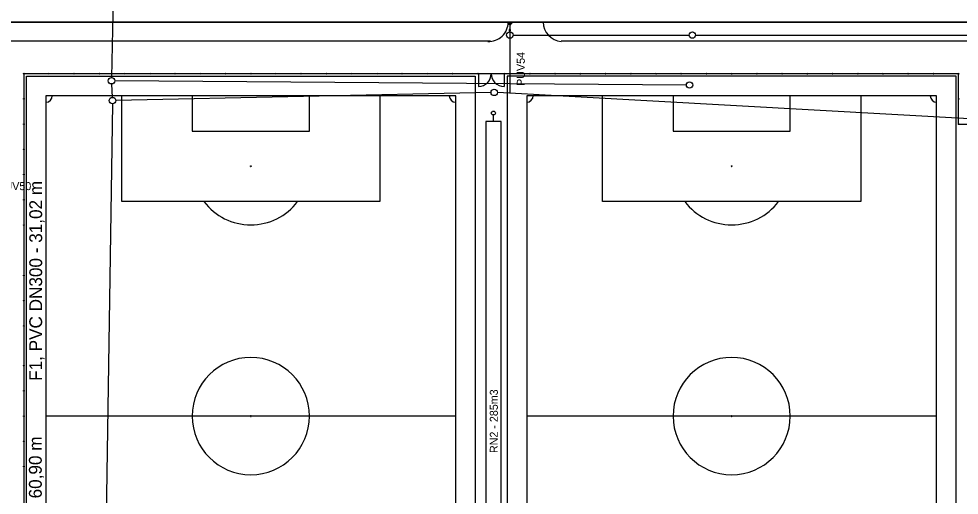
# Model space of a CAD drawing. Extents: x -264234 to -263604, y -1242346 to -1242049.
# Drawn here: x -264118.9 to -263972, y -1242253.3 to -1242179 of the extents above; entities that cross this region are included whole.
import ezdxf

# ---------------------------------------------------------------- set-up
doc = ezdxf.new("R2010")
doc.units = 0
for name, color, linetype in [('KFA_DAZDOVA_KANALIZACIA_vetva_F_popis', 7, 'Continuous'), ('KFA_JESTV_IS_DSP_-_KANAL_DAZD', 7, 'Continuous'), ('KFA_SITUACIA_DSP', 7, 'Continuous'), ('KFA_SO_40-2-II_DK_PRIPOJKY_UV_PROJEKT', 7, 'Continuous'), ('KFA_SO_40-2-II_DK_PRIPOJKY_UV_PROJEKT_popis', 7, 'Continuous')]:
    doc.layers.add(name, color=color, linetype=linetype)

msp = doc.modelspace()

# ---------------------------------------------------------------- linework, layer by layer
at = {"layer": 'KFA_JESTV_IS_DSP_-_KANAL_DAZD'}
for p, q in [((-264103.36, -1242140.62), (-264104.36, -1242188.14)), ((-264014.6, -1242189.3), (-264103.87, -1242188.64)), ((-264104.37, -1242189.14), (-264104.25, -1242191.23)), ((-264045.1, -1242190.47), (-264103.72, -1242191.72)), ((-263970.37, -1242194.6), (-264044.1, -1242190.48)), ((-264104.23, -1242192.23), (-264105.48, -1242275.06))]:
    msp.add_line(p, q, dxfattribs=at)
for centre in [(-264104.37, -1242188.64), (-264014.1, -1242189.3), (-264044.6, -1242190.46), (-264104.22, -1242191.73)]:
    msp.add_circle(centre, 0.5, dxfattribs=at)
at = {"layer": 'KFA_SITUACIA_DSP'}
for p, q in [((-264077.23, -1242179.48), (-264131.57, -1242179.48)), ((-264131.57, -1242179.48), (-263959.47, -1242179.48)), ((-263959.47, -1242179.48), (-264131.57, -1242179.48)), ((-263959.47, -1242179.48), (-264077.23, -1242179.48)), ((-264042.42, -1242179.48), (-264041.92, -1242179.48)), ((-264042.42, -1242179.77), (-264042.42, -1242179.48)), ((-264042.42, -1242179.48), (-264041.92, -1242179.77)), ((-264042.42, -1242179.48), (-264041.92, -1242179.77)), ((-264041.92, -1242179.48), (-264042.42, -1242179.48)), ((-264041.92, -1242179.77), (-264042.42, -1242179.77)), ((-264042.17, -1242179.97), (-264042.17, -1242181)), ((-264041.92, -1242179.48), (-264041.92, -1242179.77)), ((-264041.92, -1242179.77), (-264041.92, -1242179.48)), ((-264041.67, -1242181.5), (-264014.16, -1242181.5)), ((-264013.16, -1242181.5), (-263964.16, -1242181.5)), ((-264045.2, -1242182.48), (-264131.57, -1242182.48)), ((-263960.12, -1242182.48), (-264034.16, -1242182.48)), ((-264118.01, -1242187.53), (-264118.13, -1242187.53)), ((-264118.07, -1242187.59), (-264118.07, -1242187.47)), ((-263972.07, -1242187.53), (-264118.07, -1242187.53)), ((-264118.07, -1242187.53), (-264118.07, -1242294.43)), ((-264114.07, -1242187.53), (-264114.19, -1242187.53)), ((-264114.13, -1242187.59), (-264114.13, -1242187.47)), ((-264110.13, -1242187.53), (-264110.25, -1242187.53)), ((-264110.19, -1242187.59), (-264110.19, -1242187.47)), ((-264106.19, -1242187.53), (-264106.31, -1242187.53)), ((-264106.25, -1242187.59), (-264106.25, -1242187.47)), ((-264102.25, -1242187.53), (-264102.37, -1242187.53)), ((-264102.31, -1242187.59), (-264102.31, -1242187.47)), ((-264098.31, -1242187.53), (-264098.43, -1242187.53)), ((-264098.37, -1242187.59), (-264098.37, -1242187.47)), ((-264094.37, -1242187.53), (-264094.49, -1242187.53)), ((-264094.43, -1242187.59), (-264094.43, -1242187.47)), ((-264090.44, -1242187.53), (-264090.56, -1242187.53)), ((-264090.5, -1242187.59), (-264090.5, -1242187.47)), ((-264086.5, -1242187.53), (-264086.62, -1242187.53)), ((-264086.56, -1242187.59), (-264086.56, -1242187.47)), ((-264082.56, -1242187.53), (-264082.68, -1242187.53)), ((-264082.62, -1242187.59), (-264082.62, -1242187.47)), ((-264078.62, -1242187.53), (-264078.74, -1242187.53)), ((-264078.68, -1242187.59), (-264078.68, -1242187.47)), ((-264074.68, -1242187.53), (-264074.8, -1242187.53)), ((-264074.74, -1242187.59), (-264074.74, -1242187.47)), ((-264070.74, -1242187.53), (-264070.86, -1242187.53)), ((-264070.8, -1242187.59), (-264070.8, -1242187.47)), ((-264066.8, -1242187.53), (-264066.92, -1242187.53)), ((-264066.86, -1242187.59), (-264066.86, -1242187.47)), ((-264062.86, -1242187.53), (-264062.98, -1242187.53)), ((-264062.92, -1242187.59), (-264062.92, -1242187.47)), ((-264058.92, -1242187.53), (-264059.04, -1242187.53)), ((-264058.98, -1242187.59), (-264058.98, -1242187.47)), ((-264054.99, -1242187.53), (-264055.11, -1242187.53)), ((-264055.05, -1242187.59), (-264055.05, -1242187.47)), ((-264051.05, -1242187.53), (-264051.17, -1242187.53)), ((-264051.11, -1242187.59), (-264051.11, -1242187.47)), ((-264047.11, -1242187.53), (-264047.23, -1242187.53)), ((-264047.17, -1242187.59), (-264047.17, -1242187.47)), ((-264047.07, -1242187.53), (-264047.07, -1242189.53)), ((-264044.57, -1242187.53), (-264045.57, -1242187.53)), ((-264043.07, -1242187.53), (-264043.07, -1242189.53)), ((-264042.91, -1242187.53), (-264043.03, -1242187.53)), ((-264042.97, -1242187.59), (-264042.97, -1242187.47)), ((-264039.09, -1242187.53), (-264038.97, -1242187.53)), ((-264039.03, -1242187.59), (-264039.03, -1242187.47)), ((-264035.15, -1242187.53), (-264035.03, -1242187.53)), ((-264035.09, -1242187.59), (-264035.09, -1242187.47)), ((-264031.21, -1242187.53), (-264031.09, -1242187.53)), ((-264031.15, -1242187.59), (-264031.15, -1242187.47)), ((-264027.27, -1242187.53), (-264027.15, -1242187.53)), ((-264027.21, -1242187.59), (-264027.21, -1242187.47)), ((-264023.33, -1242187.53), (-264023.21, -1242187.53)), ((-264023.27, -1242187.59), (-264023.27, -1242187.47)), ((-264019.39, -1242187.53), (-264019.27, -1242187.53)), ((-264019.33, -1242187.59), (-264019.33, -1242187.47)), ((-264015.46, -1242187.53), (-264015.34, -1242187.53)), ((-264015.4, -1242187.59), (-264015.4, -1242187.47)), ((-264011.52, -1242187.53), (-264011.4, -1242187.53)), ((-264011.46, -1242187.59), (-264011.46, -1242187.47)), ((-264007.58, -1242187.53), (-264007.46, -1242187.53)), ((-264007.52, -1242187.59), (-264007.52, -1242187.47)), ((-264003.64, -1242187.53), (-264003.52, -1242187.53)), ((-264003.58, -1242187.59), (-264003.58, -1242187.47)), ((-263999.7, -1242187.53), (-263999.58, -1242187.53)), ((-263999.64, -1242187.59), (-263999.64, -1242187.47)), ((-263995.76, -1242187.53), (-263995.64, -1242187.53)), ((-263995.7, -1242187.59), (-263995.7, -1242187.47)), ((-263991.82, -1242187.53), (-263991.7, -1242187.53)), ((-263991.76, -1242187.59), (-263991.76, -1242187.47)), ((-263987.88, -1242187.53), (-263987.76, -1242187.53)), ((-263987.82, -1242187.59), (-263987.82, -1242187.47)), ((-263983.94, -1242187.53), (-263983.82, -1242187.53)), ((-263983.88, -1242187.59), (-263983.88, -1242187.47)), ((-263980.01, -1242187.53), (-263979.89, -1242187.53)), ((-263979.95, -1242187.59), (-263979.95, -1242187.47)), ((-263976.07, -1242187.53), (-263975.95, -1242187.53)), ((-263976.01, -1242187.59), (-263976.01, -1242187.47)), ((-263972.13, -1242187.53), (-263972.01, -1242187.53)), ((-263972.07, -1242187.59), (-263972.07, -1242187.47)), ((-263972.07, -1242195.41), (-263972.07, -1242187.53)), ((-264118.01, -1242191.47), (-264118.13, -1242191.47)), ((-264118.07, -1242191.41), (-264118.07, -1242191.53)), ((-264050.62, -1242190.98), (-264114.62, -1242190.98)), ((-264114.62, -1242190.98), (-264114.62, -1242290.98)), ((-264102.78, -1242207.48), (-264102.78, -1242190.98)), ((-264091.78, -1242190.98), (-264091.78, -1242196.48)), ((-264073.46, -1242196.48), (-264073.46, -1242190.98)), ((-264062.46, -1242190.98), (-264062.46, -1242207.48)), ((-264050.62, -1242290.98), (-264050.62, -1242190.98)), ((-263975.52, -1242190.98), (-264039.52, -1242190.98)), ((-264039.52, -1242190.98), (-264039.52, -1242290.98)), ((-264027.68, -1242207.48), (-264027.68, -1242190.98)), ((-264016.68, -1242190.98), (-264016.68, -1242196.48)), ((-263998.36, -1242196.48), (-263998.36, -1242190.98)), ((-263987.36, -1242190.98), (-263987.36, -1242207.48)), ((-263975.52, -1242290.98), (-263975.52, -1242190.98)), ((-263972.13, -1242191.47), (-263972.01, -1242191.47)), ((-263972.07, -1242191.41), (-263972.07, -1242191.53)), ((-264044.73, -1242194.98), (-264044.73, -1242193.98)), ((-264118.01, -1242195.41), (-264118.13, -1242195.41)), ((-264118.07, -1242195.35), (-264118.07, -1242195.47)), ((-264043.53, -1242194.98), (-264045.93, -1242194.98)), ((-264045.93, -1242194.98), (-264045.93, -1242293.98)), ((-264043.53, -1242293.98), (-264043.53, -1242194.98)), ((-263972.07, -1242195.41), (-263967.42, -1242195.41)), ((-264091.78, -1242196.48), (-264073.46, -1242196.48)), ((-264016.68, -1242196.48), (-263998.36, -1242196.48)), ((-264118.01, -1242199.34), (-264118.13, -1242199.34)), ((-264118.07, -1242199.28), (-264118.07, -1242199.4)), ((-264118.01, -1242203.28), (-264118.13, -1242203.28)), ((-264118.07, -1242203.22), (-264118.07, -1242203.34)), ((-264118.01, -1242207.22), (-264118.13, -1242207.22)), ((-264118.07, -1242207.16), (-264118.07, -1242207.28)), ((-264062.46, -1242207.48), (-264102.78, -1242207.48)), ((-263987.36, -1242207.48), (-264027.68, -1242207.48)), ((-264118.01, -1242211.16), (-264118.13, -1242211.16)), ((-264118.07, -1242211.1), (-264118.07, -1242211.22)), ((-264118.01, -1242219.03), (-264118.13, -1242219.03)), ((-264118.07, -1242218.97), (-264118.07, -1242219.09)), ((-264118.01, -1242222.97), (-264118.13, -1242222.97)), ((-264118.07, -1242222.91), (-264118.07, -1242223.03)), ((-264118.01, -1242226.91), (-264118.13, -1242226.91)), ((-264118.07, -1242226.85), (-264118.07, -1242226.97)), ((-264118.01, -1242233.11), (-264118.13, -1242233.11)), ((-264118.07, -1242233.05), (-264118.07, -1242233.17)), ((-264118.01, -1242237.04), (-264118.13, -1242237.04)), ((-264118.07, -1242236.98), (-264118.07, -1242237.1)), ((-264118.01, -1242240.98), (-264118.13, -1242240.98)), ((-264118.07, -1242241.04), (-264118.07, -1242240.92)), ((-264050.62, -1242240.98), (-264114.62, -1242240.98)), ((-263975.52, -1242240.98), (-264039.52, -1242240.98)), ((-264118.01, -1242244.92), (-264118.13, -1242244.92)), ((-264118.07, -1242244.98), (-264118.07, -1242244.86)), ((-264118.01, -1242248.86), (-264118.13, -1242248.86)), ((-264118.07, -1242248.92), (-264118.07, -1242248.8))]:
    msp.add_line(p, q, dxfattribs=at)
for points in [[(-264117.67, -1242187.93), (-264047.57, -1242187.93), (-264047.57, -1242294.03), (-264117.67, -1242294.03)], [(-264042.57, -1242294.03), (-263972.47, -1242294.03), (-263972.47, -1242187.93), (-264042.57, -1242187.93)]]:
    msp.add_lwpolyline(points, close=True, dxfattribs=at)
for centre, radius in [((-264042.17, -1242179.87), 0.1), ((-264042.17, -1242181.5), 0.5), ((-264013.66, -1242181.5), 0.5), ((-264118.07, -1242187.53), 0.06), ((-264114.13, -1242187.53), 0.06), ((-264110.19, -1242187.53), 0.06), ((-264106.25, -1242187.53), 0.06), ((-264102.31, -1242187.53), 0.06), ((-264098.37, -1242187.53), 0.06), ((-264094.43, -1242187.53), 0.06), ((-264090.5, -1242187.53), 0.06), ((-264086.56, -1242187.53), 0.06), ((-264082.62, -1242187.53), 0.06), ((-264078.68, -1242187.53), 0.06), ((-264074.74, -1242187.53), 0.06), ((-264070.8, -1242187.53), 0.06), ((-264066.86, -1242187.53), 0.06), ((-264062.92, -1242187.53), 0.06), ((-264058.98, -1242187.53), 0.06), ((-264055.05, -1242187.53), 0.06), ((-264051.11, -1242187.53), 0.06), ((-264047.17, -1242187.53), 0.06), ((-264042.97, -1242187.53), 0.06), ((-264039.03, -1242187.53), 0.06), ((-264035.09, -1242187.53), 0.06), ((-264031.15, -1242187.53), 0.06), ((-264027.21, -1242187.53), 0.06), ((-264023.27, -1242187.53), 0.06), ((-264019.33, -1242187.53), 0.06), ((-264015.4, -1242187.53), 0.06), ((-264011.46, -1242187.53), 0.06), ((-264007.52, -1242187.53), 0.06), ((-264003.58, -1242187.53), 0.06), ((-263999.64, -1242187.53), 0.06), ((-263995.7, -1242187.53), 0.06), ((-263991.76, -1242187.53), 0.06), ((-263987.82, -1242187.53), 0.06), ((-263983.88, -1242187.53), 0.06), ((-263979.95, -1242187.53), 0.06), ((-263976.01, -1242187.53), 0.06), ((-263972.07, -1242187.53), 0.06), ((-264118.07, -1242191.47), 0.06), ((-263972.07, -1242191.47), 0.06), ((-264044.73, -1242193.68), 0.3), ((-264118.07, -1242195.41), 0.06), ((-263972.07, -1242195.41), 0.06), ((-264118.07, -1242199.34), 0.06), ((-264082.62, -1242201.98), 0.06), ((-264007.52, -1242201.98), 0.06), ((-264118.07, -1242203.28), 0.06), ((-264118.07, -1242207.22), 0.06), ((-264118.07, -1242211.16), 0.06), ((-264118.07, -1242219.03), 0.06), ((-264118.07, -1242222.97), 0.06), ((-264118.07, -1242226.91), 0.06), ((-264118.07, -1242233.11), 0.06), ((-264118.07, -1242237.04), 0.06), ((-264118.07, -1242240.98), 0.06), ((-264118.07, -1242244.92), 0.06), ((-264118.07, -1242248.86), 0.06)]:
    msp.add_circle(centre, radius, dxfattribs=at)
for centre, radius, start, end in [((-264045.41, -1242179.5), 2.99, 266.0314, 0.25), ((-264033.95, -1242179.5), 2.99, 179.75, 266.0314), ((-264042.17, -1242180.74), 0.125, 0, 180), ((-264042.17, -1242180.74), 0.125, 180, 0), ((-264047.07, -1242187.53), 2, 270, 360), ((-264043.07, -1242187.53), 2, 180, 270), ((-264114.62, -1242190.98), 1, 270, 360), ((-264050.62, -1242190.98), 1, 180, 270), ((-264039.52, -1242190.98), 1, 270, 360), ((-263975.52, -1242190.98), 1, 180, 270), ((-264082.62, -1242201.98), 0.0303, 90, 270), ((-264082.62, -1242201.98), 0.0303, 270, 90), ((-264007.52, -1242201.98), 0.0303, 90, 270), ((-264007.52, -1242201.98), 0.0303, 270, 90), ((-264082.62, -1242201.98), 9.15, 216.9482, 323.0518), ((-264007.52, -1242201.98), 9.15, 216.9482, 323.0518), ((-264082.62, -1242240.98), 9.15, 360, 180), ((-264007.52, -1242240.98), 9.15, 360, 180), ((-264082.62, -1242240.98), 9.15, 180, 360), ((-264082.62, -1242240.98), 0.0605, 90, 270), ((-264082.62, -1242240.98), 0.0605, 270, 90), ((-264007.52, -1242240.98), 9.15, 180, 360), ((-264007.52, -1242240.98), 0.0605, 90, 270), ((-264007.52, -1242240.98), 0.0605, 270, 90)]:
    msp.add_arc(centre, radius, start, end, dxfattribs=at)
at = {"layer": 'KFA_SO_40-2-II_DK_PRIPOJKY_UV_PROJEKT'}
msp.add_lwpolyline([(-264042.17, -1242179.97), (-264042.17, -1242190.59)], dxfattribs=at)

# ---------------------------------------------------------------- texts
at = {"layer": 'KFA_DAZDOVA_KANALIZACIA_vetva_F_popis'}
for s, p in [('F1, PVC DN300 - 31,02 m', (-264115.21, -1242235.48)), ('F1, PVC DN300 - 60,90 m', (-264115.27, -1242275.38))]:
    msp.add_text(s, height=2, rotation=90, dxfattribs=at).set_placement(p)
at = {"layer": 'KFA_SITUACIA_DSP'}
msp.add_text('RN2 - 285m3', height=1.25, rotation=90, dxfattribs=at).set_placement((-264044.04, -1242246.75))
at = {"layer": 'KFA_SO_40-2-II_DK_PRIPOJKY_UV_PROJEKT_popis'}
msp.add_text('PUV54', height=1.25, rotation=90, dxfattribs=at).set_placement((-264039.83, -1242189.44))
msp.add_text('PUV50', height=1.25, dxfattribs=at).set_placement((-264122.2, -1242205.71))

doc.saveas('drawing.dxf')
